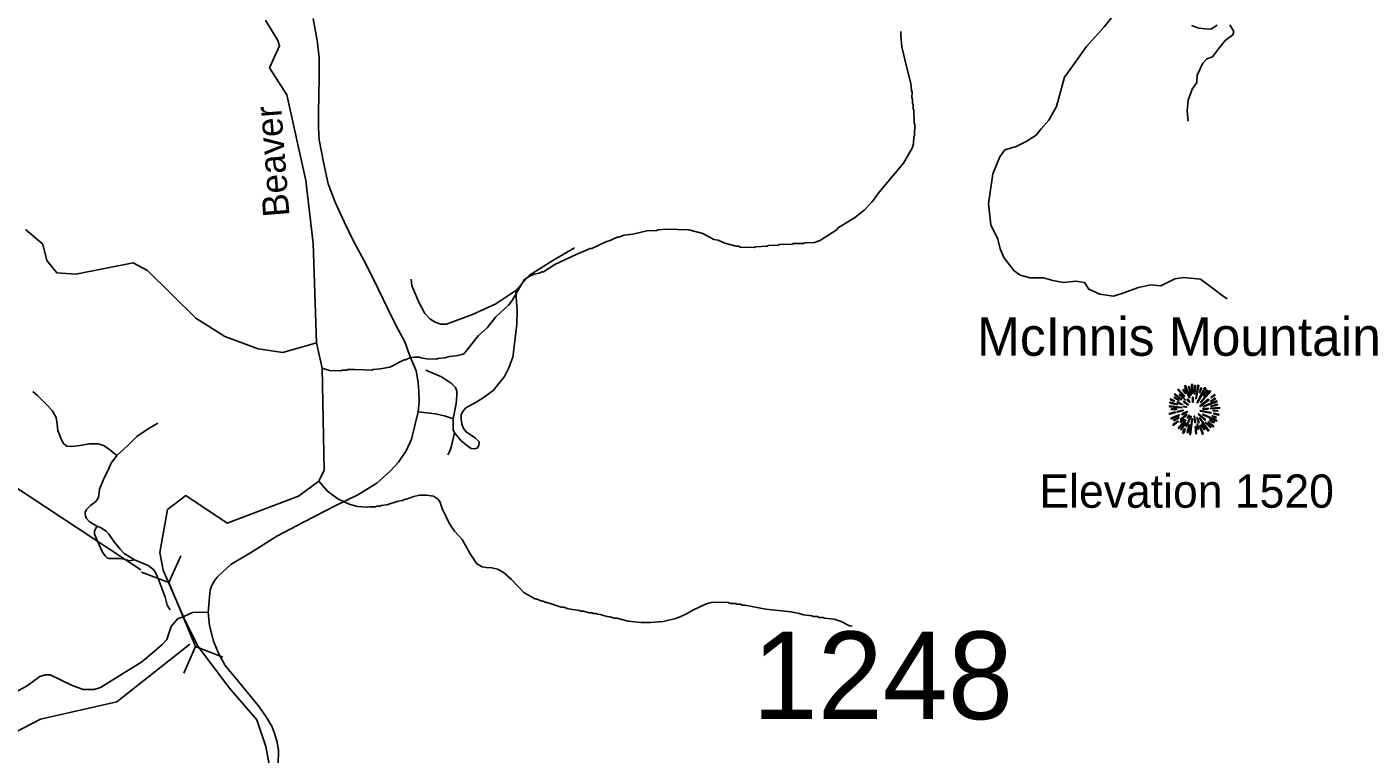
# Model space of a CAD drawing. Extents: x 1248089 to 1457196, y 820910 to 988753.
# Drawn here: x 1305188 to 1312834, y 839954 to 844107 of the extents above; entities that cross this region are included whole.
import ezdxf

# ---------------------------------------------------------------- set-up
doc = ezdxf.new("R2010")
doc.units = 0
for name, color, linetype in [('Exist Geographical Mountain Summit CELL', 7, 'Continuous'), ('Exist Geographical Mountain Summit Elevation Number Label', 7, 'Continuous'), ('Exist Geographical Mountain Summit Label', 7, 'Continuous'), ('Exist Hydrographic Creek Single Shore', 7, 'Continuous'), ('Exist Hydrographic Misc Water Feature', 7, 'Continuous'), ('Exist Road Non-System Type 51', 7, 'Continuous'), ('Exist Road Secondary Structure Culvert CELL', 7, 'Continuous'), ('Exist Road Secondary Type 51 Attributed', 7, 'Continuous'), ('Prop Guardrail Anchor Unit CELL', 7, 'Continuous'), ('Prop Lane Lines', 7, 'Continuous'), ('Scratch_Level_4', 7, 'Continuous')]:
    doc.layers.add(name, color=color, linetype=linetype)

msp = doc.modelspace()

# ---------------------------------------------------------------- linework, layer by layer
at = {"layer": 'Exist Geographical Mountain Summit CELL'}
for points in [[(1311759.1, 842033), (1311795.1, 841995.6), (1311798.4, 841998.1), (1311763.1, 842037.8)], [(1311786.7, 842034.5), (1311802.3, 842012.7), (1311804.2, 842014.1), (1311790.7, 842038.5)], [(1311797.6, 842056.3), (1311823.8, 841989.4), (1311826.7, 841990.5), (1311802.7, 842058.8)], [(1311831.4, 842004.3), (1311833.9, 842005), (1311824.9, 842053), (1311820.5, 842051.9)], [(1311836.2, 842065.7), (1311840.2, 842013.7), (1311843.4, 842014.1), (1311842, 842066.8)], [(1311852.2, 842011.6), (1311856.1, 842011.6), (1311859.7, 842058.8), (1311854.3, 842058.8)], [(1311864.1, 841983.2), (1311879, 842060.3), (1311873.6, 842062.1), (1311860.9, 841984)], [(1311867.4, 841961.4), (1311870.3, 841959.6), (1311919, 842044.2), (1311913.5, 842047.9)], [(1311881.9, 842018.5), (1311885.2, 842017.3), (1311894.7, 842044.2), (1311889.9, 842046.1)], [(1311888.5, 841962.9), (1311890.7, 841960.7), (1311946.2, 842025), (1311942.2, 842029.8)], [(1311925.9, 842034.5), (1311904.8, 842001), (1311907.8, 841999.9), (1311930.2, 842031.2)], [(1311710.4, 841938.2), (1311782.4, 841931.2), (1311782.7, 841934.2), (1311710.4, 841943.2)], [(1311713, 841959.2), (1311754.4, 841949.8), (1311755.5, 841953.1), (1311714.1, 841964)], [(1311715.9, 841978.5), (1311738.4, 841969.8), (1311739.5, 841972.7), (1311717.3, 841983.6)], [(1311737.7, 841989.4), (1311763.5, 841973), (1311765.7, 841975.6), (1311740.6, 841993.4)], [(1311738.8, 842008.3), (1311778.4, 841977.8), (1311780.6, 841980), (1311742.4, 842012.7)], [(1311754.4, 841961.4), (1311784.9, 841949.5), (1311786, 841951.6), (1311756.6, 841965.5)], [(1311767.1, 842005.4), (1311799.8, 841976.3), (1311802, 841978.5), (1311770, 842010.5)], [(1311790.7, 841966.9), (1311815.8, 841947.9), (1311817.9, 841950.9), (1311793.3, 841970.1)], [(1311791.1, 841937.1), (1311808.2, 841934.9), (1311808.6, 841937.1), (1311791.8, 841941.4)], [(1311810.4, 841980), (1311824.2, 841963.6), (1311826.3, 841965.8), (1311813.6, 841982.9)], [(1311841.6, 841992.3), (1311843, 841963.2), (1311845.6, 841963.6), (1311845.6, 841992.7)], [(1311885.2, 841942.9), (1311887, 841940.4), (1311935.7, 841976.3), (1311932.5, 841980.7)], [(1311902.2, 841940), (1311903.4, 841937.8), (1311981.5, 841966.5), (1311979.7, 841971.2)], [(1311946.2, 841968), (1311973.8, 841982.9), (1311971, 841987.9), (1311944.8, 841970.5)], [(1311946.2, 841990.9), (1311948.1, 841988.3), (1311971, 842004.6), (1311967.3, 842008.3)], [(1311948.1, 841940), (1311984.8, 841946.5), (1311983.3, 841952), (1311946.6, 841942.2)], [(1311709, 841900.4), (1311710.4, 841895.3), (1311746.4, 841905.8), (1311744.2, 841909.1)], [(1311718.7, 841872.7), (1311721.3, 841868.1), (1311766.7, 841888), (1311765.3, 841892.7)], [(1311722.5, 841920.7), (1311752.2, 841922.2), (1311752.2, 841925.8), (1311721.3, 841925.8)], [(1311736.2, 841856.8), (1311765.3, 841873.5), (1311763.1, 841877.1), (1311734, 841861.8)], [(1311754.8, 841911.7), (1311755.8, 841906.9), (1311788.9, 841915.3), (1311788.2, 841918.9)], [(1311760.9, 841816.4), (1311763.8, 841813.9), (1311804.6, 841861.5), (1311801.6, 841863.6)], [(1311776.2, 841847.7), (1311795.5, 841865.8), (1311792.1, 841868.1), (1311771.8, 841850.9)], [(1311772.5, 841866.2), (1311775.4, 841862.5), (1311810, 841890.9), (1311808.2, 841893.5)], [(1311782.4, 841897.5), (1311784.6, 841892.7), (1311813.3, 841908), (1311812.2, 841911.3)], [(1311804.2, 841826.3), (1311808.6, 841824.5), (1311835.1, 841882.9), (1311832.5, 841883.7)], [(1311811.1, 841875.6), (1311814.3, 841872.7), (1311824.5, 841889.1), (1311822.7, 841890.5)], [(1311825.6, 841780.8), (1311830.3, 841779.7), (1311843, 841869.1), (1311839.8, 841869.9)], [(1311851, 841884.8), (1311855, 841847.7), (1311859.4, 841848), (1311854.3, 841885.5)], [(1311867.1, 841876), (1311875.8, 841846.2), (1311879.8, 841848), (1311869.2, 841877.1)], [(1311875.4, 841896.4), (1311913.9, 841861.1), (1311916.4, 841865.5), (1311877.2, 841898.6)], [(1311881.6, 841873.8), (1311932.1, 841799), (1311935.7, 841801.9), (1311884.1, 841874.9)], [(1311886.6, 841913.5), (1311947.4, 841901.5), (1311948.4, 841905.8), (1311887.7, 841917.1)], [(1311900.4, 841893.9), (1311978.6, 841855.7), (1311980.4, 841861.1), (1311902, 841896.7)], [(1311901.2, 841927.3), (1311901.2, 841924.4), (1311931.3, 841924.4), (1311932.1, 841929.4)], [(1311939.7, 841859.7), (1311964.8, 841846.6), (1311967.3, 841850.3), (1311941.9, 841863.6)], [(1311944.4, 841926.2), (1311996.8, 841929.4), (1311997.1, 841934.2), (1311944.8, 841929.4)], [(1311953.9, 841883.7), (1311975, 841875.6), (1311976.8, 841880), (1311955.3, 841886.9)], [(1311959.3, 841914.2), (1311985.9, 841912), (1311985.9, 841916.3), (1311959.7, 841917.4)], [(1311963.4, 841897.1), (1311991.7, 841889.8), (1311992.4, 841895.3), (1311964.4, 841901.5)], [(1311730, 841836), (1311732.9, 841832), (1311761.3, 841853.1), (1311758.7, 841856.4)], [(1311800.9, 841847.7), (1311775.8, 841808.4), (1311779, 841805.9), (1311804.9, 841845.5)], [(1311786, 841789.2), (1311790.7, 841786.3), (1311801.6, 841811), (1311798.4, 841813.2)], [(1311815.8, 841791), (1311827.8, 841833.8), (1311824.2, 841834.2), (1311811.4, 841792)], [(1311857.2, 841826.3), (1311860.9, 841783.8), (1311864.9, 841784.8), (1311861.5, 841826.3)], [(1311876.8, 841809.5), (1311871.4, 841839.4), (1311868.1, 841839.4), (1311872.5, 841808.4)], [(1311881.6, 841831), (1311899, 841781.2), (1311903.4, 841783), (1311884.5, 841831.7)], [(1311892.1, 841836.8), (1311908.1, 841807.3), (1311912.1, 841809.5), (1311895.8, 841838.2)], [(1311913.9, 841848), (1311944, 841818.9), (1311947.4, 841821.5), (1311916.1, 841850.5)], [(1311930.6, 841848.7), (1311961.1, 841822.9), (1311964.4, 841826.6), (1311932.5, 841851.3)]]:
    msp.add_lwpolyline(points, close=True, dxfattribs=at)
at = {"layer": 'Exist Hydrographic Creek Single Shore'}
for points in [[(1306842.9, 842302.4), (1306822.9, 842870.7), (1306780.8, 843229.3), (1306672.7, 843719.6), (1306574.5, 843872.4), (1306631.8, 843998), (1306620.9, 844029.8), (1306550, 844144.5)], [(1306086.1, 840728.5), (1305967.6, 841005.4), (1305947.5, 841105.8), (1305991.6, 841350.7), (1306095.9, 841431), (1306332.7, 841274.4), (1306738.9, 841428), (1306855.3, 841512.4), (1306884.9, 841576), (1306875.3, 842157.6), (1306842.9, 842302.4)], [(1306249.8, 839379.5), (1306301.9, 839486.8), (1306471.9, 839608.2), (1306524.9, 839741.6), (1306581.4, 839845.1), (1306553.3, 839997.6), (1306501.2, 840150.2), (1306344.7, 840330.9), (1306164.2, 840571.8), (1306086.1, 840728.5)]]:
    msp.add_lwpolyline(points, dxfattribs=at)
at = {"layer": 'Exist Hydrographic Misc Water Feature'}
for points in [[(1310177.2, 844080.1), (1310176.6, 844056.1), (1310183.2, 843992), (1310209.7, 843879.7), (1310234.4, 843782.9), (1310237.5, 843742.8), (1310241.4, 843734.7), (1310240.7, 843702.7), (1310244.5, 843694.6), (1310243.9, 843670.6), (1310247.7, 843662.5), (1310247.1, 843638.6), (1310251, 843630.5), (1310253.4, 843558.4), (1310257.2, 843550.4), (1310255.7, 843486.4), (1310251.5, 843478.5), (1310250.6, 843438.5), (1310242.1, 843414.7), (1310192.2, 843328), (1310054.4, 843163.2), (1310013.2, 843108.1), (1309968.1, 843061.2), (1309913.1, 843016.5), (1309821.9, 842960.7), (1309807.5, 842947), (1309718.2, 842889.1), (1309685.9, 842875.9), (1309629.8, 842873.2), (1309621.7, 842869.4), (1309565.7, 842870.7), (1309557.6, 842866.9), (1309485.6, 842864.6), (1309477.6, 842860.7), (1309421.5, 842858.1), (1309413.4, 842854.3), (1309349.3, 842851.8), (1309341.2, 842848), (1309261.2, 842849.8), (1309253.3, 842854), (1309237.4, 842854.4), (1309173.8, 842871.9), (1309134.1, 842888.8), (1309110.2, 842893.3), (1309047, 842926.8), (1308967.5, 842948.7), (1308839.6, 842951.7), (1308791.5, 842948.8), (1308783.4, 842945), (1308727.3, 842942.4), (1308646.9, 842924.2), (1308598.7, 842917.3), (1308566.5, 842906.1), (1308558.5, 842906.3), (1308518, 842887.2), (1308493.8, 842879.8), (1308413, 842841.7), (1308405, 842841.9), (1308324.3, 842807.8), (1308203, 842750.7), (1308138, 842708.2), (1308130, 842708.4), (1308113.8, 842700.8), (1308083.6, 842695.5), (1308051.3, 842680.2), (1308026.9, 842662.8), (1307958.2, 842544.5), (1307939.7, 842520.9), (1307866.2, 842450.6), (1307816.7, 842387.8), (1307767.7, 842344.9), (1307687.5, 842244.8), (1307679.4, 842239), (1307639.1, 842228), (1307599, 842224.9), (1307574.8, 842217.5), (1307534.7, 842214.4), (1307526.7, 842210.6), (1307470.7, 842211.9), (1307438.8, 842216.7), (1307430.8, 842220.8), (1307396.9, 842221.6), (1307374.9, 842218.2), (1307350.6, 842206.7), (1307342.6, 842206.9), (1307261.6, 842164.8), (1307205.4, 842154.1), (1307165.3, 842151.1), (1307157.2, 842147.3), (1307061.3, 842151.5), (1307021.3, 842150.4), (1307013.2, 842146.7), (1306989.2, 842147.2), (1306981.1, 842143.4), (1306917.1, 842144.9), (1306875.3, 842157.6)], [(1306842.9, 842302.4), (1306649.8, 842247.1), (1306508.8, 842269.7), (1306318.8, 842339.1), (1306153.9, 842444.2), (1305876.9, 842715.7), (1305794.8, 842760), (1305467.8, 842694.4), (1305359.8, 842703.1), (1305302.8, 842773.2), (1305279.8, 842865.6), (1305181.8, 842949.6)], [(1309900.4, 840685.2), (1309884.4, 840687.6), (1309836.9, 840712.7), (1309797.2, 840725.6), (1309741.4, 840731), (1309733.5, 840735.1), (1309709.5, 840735.7), (1309701.6, 840739.9), (1309677.6, 840740.5), (1309669.7, 840744.7), (1309621.8, 840749.7), (1309597.9, 840758.3), (1309550.2, 840767.4), (1309406.5, 840782.8), (1309287, 840805.6), (1309271, 840806), (1309263.1, 840810.2), (1309239.1, 840810.7), (1309231.2, 840814.9), (1309207.2, 840815.5), (1309191.3, 840819.9), (1309103.4, 840821.9), (1309087.3, 840818.3), (1309063.2, 840810.8), (1308990.4, 840776.5), (1308957.9, 840757.3), (1308917.5, 840738.3), (1308885.2, 840727), (1308820.9, 840712.5), (1308748.7, 840706.2), (1308692.7, 840705.5), (1308620.9, 840713.2), (1308557.3, 840730.7), (1308541.3, 840731.1), (1308517.5, 840739.6), (1308501.5, 840740), (1308461.7, 840753), (1308445.8, 840753.3), (1308437.9, 840757.5), (1308421.9, 840757.9), (1308414, 840762.1), (1308398, 840762.4), (1308366.2, 840771.2), (1308350.2, 840771.6), (1308342.3, 840775.7), (1308278.5, 840785.3), (1308254.6, 840793.8), (1308238.6, 840794.2), (1308159.3, 840820), (1308151.3, 840820.2), (1308135.5, 840828.6), (1308127.5, 840828.8), (1308095.7, 840841.5), (1308087.7, 840841.7), (1308024.6, 840877.2), (1307954.2, 840952.8), (1307907.2, 840993.9), (1307875.6, 841010.7), (1307843.7, 841019.4), (1307811.7, 841020.1), (1307787.8, 841024.7), (1307758.2, 841041.4), (1307719.6, 841098.3), (1307673.3, 841179.4), (1307630.5, 841228.4), (1307601.3, 841269), (1307559.4, 841358), (1307546.3, 841396.3), (1307532.7, 841412.6), (1307509, 841427.2), (1307469.1, 841434.1), (1307429.1, 841433), (1307396.9, 841425.8), (1307356.5, 841410.7), (1307348.5, 841410.9), (1307332.4, 841403.3), (1307308.3, 841399.9), (1307243.8, 841377.4), (1307211.7, 841374.1), (1307203.6, 841370.3), (1307187.7, 841370.7), (1307179.6, 841366.9), (1307147.6, 841367.7), (1307131.5, 841364), (1307075.6, 841369.3), (1307027.9, 841382.4), (1306964.6, 841411.9), (1306905.5, 841455.3), (1306855.3, 841512.4)], [(1306118.8, 840583.6), (1305702.9, 840253.8), (1305266.8, 840154.3), (1305064.9, 840050)]]:
    msp.add_lwpolyline(points, dxfattribs=at)
at = {"layer": 'Exist Road Non-System Type 51'}
for points in [[(1311065.2, 843652), (1311112.4, 843818.9), (1311142.8, 843861.4), (1311237.2, 843995.5), (1311338.3, 844106.8), (1311449.6, 844244.2)], [(1312055, 844119), (1312078.5, 844081.1), (1312073.1, 844061.2), (1312028, 844028.7), (1311990.1, 843981.8), (1311955.8, 843936.6), (1311925.1, 843924), (1311901.6, 843898.7), (1311869.1, 843831.8), (1311867.3, 843788.5), (1311840.2, 843750.6), (1311816.8, 843689.2), (1311811.4, 843627.7), (1311818.6, 843568.1)], [(1311837.5, 844114.8), (1311879, 844100.4), (1311916.9, 844095), (1311946.7, 844093.8), (1311982.8, 844117.2)], [(1311065.2, 843652), (1311021.6, 843573.4), (1310979, 843525.5), (1310949.8, 843488.2), (1310896.6, 843453.6), (1310835.4, 843424.4), (1310771.6, 843405.7), (1310742.4, 843365.8), (1310702.5, 843267.4), (1310678.6, 843097.1), (1310691.9, 842977.3), (1310731.7, 842894.8), (1310745, 842839), (1310766.3, 842791.1), (1310822.1, 842716.6), (1310859.4, 842689.9), (1310915.2, 842674), (1310992.3, 842674), (1311045.5, 842658), (1311106.7, 842647.4), (1311175.8, 842655.4), (1311226.3, 842647.4), (1311250.2, 842610.1), (1311314.1, 842580.9), (1311391.2, 842570.2), (1311444.3, 842586.2), (1311534.8, 842618.1), (1311603.9, 842634.1), (1311662.4, 842628.7), (1311742.2, 842668.7), (1311792.7, 842676.6), (1311888.4, 842666), (1311930.9, 842634.1), (1312010.7, 842575.5), (1312040, 842554.2)], [(1307980.3, 842601.9), (1308057, 842690.2), (1308191.9, 842773.6), (1308314.9, 842845.6)], [(1307980.3, 842601.9), (1307865.7, 842525), (1307732.5, 842464.5), (1307584.2, 842410.5), (1307552.1, 842410.5), (1307520.1, 842420.3), (1307488.1, 842440), (1307461.1, 842471), (1307424, 842538.1), (1307386.9, 842629.7), (1307381.9, 842667.3)], [(1307629.7, 841788.9), (1307668.5, 841743.1), (1307705.5, 841713.7), (1307725.8, 841700.6), (1307744.3, 841697.3), (1307759.5, 841702.2), (1307769.6, 841717), (1307771.3, 841738.2), (1307749.4, 841759.5), (1307697.1, 841795.5), (1307680.3, 841813.5), (1307671.8, 841839.6), (1307668.5, 841869.1), (1307668.5, 841892), (1307675.2, 841908.3), (1307695.4, 841931.2), (1307752.7, 841964), (1307793.2, 841988.5), (1307850.5, 842031), (1307915.4, 842111.2), (1307939, 842160.3), (1307962.6, 842220.8), (1307971.1, 842282.9), (1307986.2, 842408.9), (1307987.9, 842487.4), (1307982, 842564.3), (1307980.3, 842601.9)], [(1307621.3, 841869.1), (1307639.8, 841955.8), (1307643.2, 842003.2), (1307643.2, 842027.8), (1307636.4, 842047.4), (1307612.8, 842070.3), (1307555.5, 842109.5), (1307466.2, 842147.2)], [(1305702.9, 841659.7), (1305652.3, 841699), (1305627, 841717), (1305596.7, 841726.8), (1305544.4, 841726.8), (1305492.2, 841717), (1305443.3, 841710.4), (1305416.3, 841713.7), (1305396.1, 841730.1), (1305382.6, 841757.9), (1305365.7, 841802), (1305362.4, 841838), (1305355.6, 841877.3), (1305333.7, 841916.5), (1305298.3, 841952.5), (1305249.4, 842003.2), (1305223.3, 842026.1)], [(1307421.5, 841910), (1307521.8, 841898.5), (1307579.1, 841883.8), (1307621.3, 841869.1)], [(1307621.3, 841869.1), (1307621.3, 841806.9), (1307629.7, 841788.9)], [(1305702.9, 841659.7), (1305766.9, 841718.6), (1305815.8, 841767.7), (1305886.6, 841816.7), (1305937.2, 841844.6)], [(1307629.7, 841788.9), (1307611.1, 841707.2), (1307601, 841681), (1307590.9, 841663)], [(1305589.1, 841257.3), (1305545.3, 841283.5), (1305528.4, 841299.9), (1305523.4, 841312.9), (1305521.7, 841334.2), (1305528.4, 841352.2), (1305552, 841375.1), (1305582.4, 841396.4), (1305597.5, 841420.9), (1305604.3, 841468.3), (1305631.2, 841535.4), (1305648.9, 841568.1), (1305670.9, 841615.6), (1305702.9, 841659.7)], [(1305589.1, 841257.3), (1305575.6, 841227.9), (1305575.6, 841209.9), (1305590.8, 841175.5), (1305621.1, 841108.5), (1305636.3, 841087.2), (1305646.4, 841075.8), (1305656.5, 841072.5), (1305681.8, 841070.9), (1305718.9, 841072.5), (1305744.2, 841067.6), (1305772.8, 841057.8), (1305802.3, 841064.3)], [(1305802.3, 841064.3), (1305745, 841100.3), (1305721.4, 841124.8), (1305687.7, 841167.4), (1305657.4, 841211.5), (1305640.5, 841227.9), (1305609.3, 841249.1), (1305589.1, 841257.3)], [(1306006.3, 840778.1), (1305989.5, 840805.9), (1305977.7, 840851.7), (1305943.9, 840943.3), (1305925.4, 840987.4), (1305913.6, 841007.1), (1305881.6, 841031.6), (1305802.3, 841064.3)]]:
    msp.add_lwpolyline(points, dxfattribs=at)
at = {"layer": 'Exist Road Secondary Structure Culvert CELL'}
for p, q in [((1306067.3, 841087.3), (1305999.5, 840935.1)), ((1305843.9, 840994.5), (1305999.5, 840935.1)), ((1305999.5, 840935.1), (1306151.7, 840568.7)), ((1306083.9, 840416.5), (1306151.7, 840568.7)), ((1306307.3, 840509.3), (1306151.7, 840568.7))]:
    msp.add_line(p, q, dxfattribs=at)
at = {"layer": 'Exist Road Secondary Type 51 Attributed'}
for points in [[(1306823.1, 844154.2), (1306846.7, 844029.9), (1306856.8, 843931.7), (1306856.8, 843814), (1306854.2, 843617.7), (1306852.6, 843531), (1306857.6, 843462.3), (1306884.6, 843324.9), (1306909, 843210.4), (1306949.5, 843105.7), (1307000.1, 842994.5), (1307051.5, 842886.5), (1307113.9, 842770.4)], [(1307113.9, 842770.4), (1307167.8, 842665.7), (1307251.2, 842493.9), (1307296.8, 842400.7), (1307345.6, 842309.1), (1307374.3, 842228.9), (1307410.5, 842142.3), (1307422.3, 842076.8), (1307425.7, 842022.8), (1307427.4, 841968.9), (1307421.5, 841910), (1307383.6, 841753), (1307353.2, 841685.9), (1307309.4, 841622.1), (1307262.2, 841569.8), (1307186.3, 841502.7), (1307077.6, 841435.6), (1306949.5, 841371.8), (1306772.5, 841281.9), (1306615.7, 841198.4), (1306480.9, 841113.4), (1306352.7, 841038.1), (1306307.2, 840995.6), (1306275.2, 840964.5), (1306258.3, 840941.6), (1306243.2, 840913.8), (1306236, 840890.5), (1306230.4, 840852), (1306223.8, 840764.3)], [(1306223.8, 840764.3), (1306173.8, 840765.5), (1306134.7, 840762.6), (1306084.2, 840741.6), (1306049.5, 840727.1), (1306011.9, 840683.8), (1305987.4, 840609.3), (1305961.6, 840580.4), (1305915.1, 840541.3), (1305844.7, 840481.8), (1305609.3, 840334.8), (1305572.2, 840323.3), (1305509.9, 840323.3), (1305444.1, 840347.9), (1305322.7, 840406.7), (1305292.4, 840406.7), (1305262.1, 840398.6), (1305191.3, 840344.6), (1305117.1, 840305.3)], [(1306223.8, 840764.3), (1306230.5, 840689.7), (1306254.1, 840599.8), (1306281.1, 840534.3), (1306321.6, 840460.7), (1306395.7, 840372.4), (1306508.7, 840231.7), (1306550.8, 840172.8), (1306586.2, 840114), (1306604.8, 840068.2), (1306618.2, 840024), (1306625, 839974.9), (1306623.3, 839898)]]:
    msp.add_lwpolyline(points, dxfattribs=at)
at = {"layer": 'Prop Guardrail Anchor Unit CELL'}
msp.add_lwpolyline([(1305838.7, 841008), (1303757.6, 842379.6), (1302669.8, 843987.7)], dxfattribs=at)

# ---------------------------------------------------------------- texts
at = {"layer": 'Exist Geographical Mountain Summit Elevation Number Label'}
msp.add_text('Elevation 1520', height=190, dxfattribs=at).set_placement((1310968.6, 841361.6))
at = {"layer": 'Exist Geographical Mountain Summit Label'}
msp.add_text('McInnis Mountain', height=220, dxfattribs=at).set_placement((1310612, 842229.2))
at = {"layer": 'Prop Lane Lines'}
msp.add_text('1248', height=500, dxfattribs=at).set_placement((1309330.7, 840154.8))
at = {"layer": 'Scratch_Level_4'}
msp.add_text('Beaver', height=150, rotation=94.39722, dxfattribs=at).set_placement((1306688.4, 843027.3))

doc.saveas('drawing.dxf')
